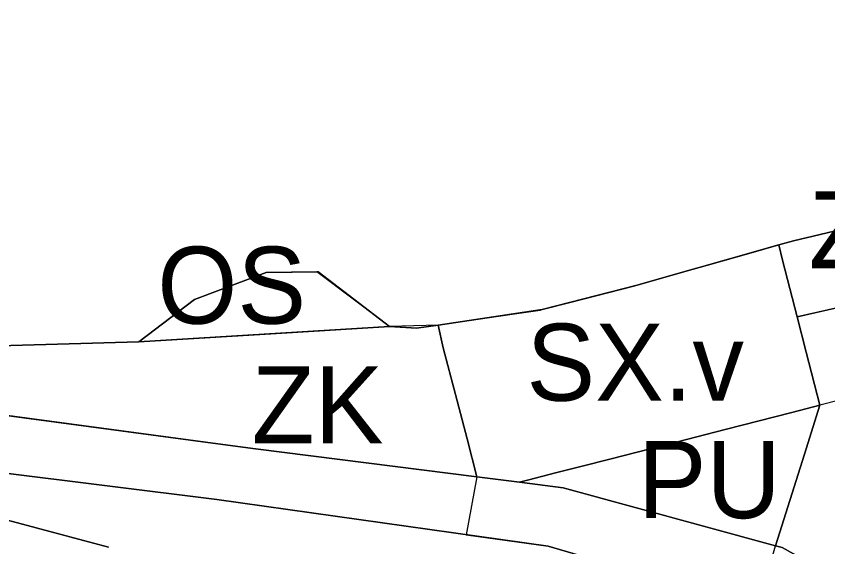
# Model space of a CAD drawing. Extents: x -555509 to -553005, y -1186756 to -1182560.
# Drawn here: x -554216.4 to -554068.9, y -1185302.9 to -1185206.5 of the extents above; entities that cross this region are included whole.
import ezdxf

# ---------------------------------------------------------------- set-up
doc = ezdxf.new("R2010")
doc.units = 0
for name, color, linetype in [('Level 15', 7, 'Continuous'), ('Level 26', 7, 'Continuous'), ('Level 36', 7, 'Continuous'), ('Level 52', 7, 'Continuous'), ('Level 59', 7, 'Continuous'), ('Level 6', 7, 'Continuous'), ('OBRYS_PLOCH', 7, 'Continuous'), ('stav_DS', 7, 'Continuous'), ('stav_OS', 7, 'Continuous'), ('stav_PU', 7, 'Continuous'), ('stav_SX', 7, 'Continuous'), ('stav_ZK', 7, 'Continuous'), ('stav_ZZ', 7, 'Continuous')]:
    doc.layers.add(name, color=color, linetype=linetype)

msp = doc.modelspace()

# ---------------------------------------------------------------- linework, layer by layer
at = {"layer": 'Level 15'}
for points in [[(-554070.29, -1185277.21), (-554075.36, -1185278.51), (-554087.47, -1185281.6), (-554096.17, -1185283.83), (-554108.47, -1185286.99), (-554113.5, -1185288.27), (-554118.34, -1185289.51), (-554123.18, -1185290.75), (-554124.88, -1185291.19)], [(-554078.34, -1185302.74), (-554073.1, -1185286.11), (-554070.29, -1185277.21)], [(-554124.88, -1185291.19), (-554116.97, -1185292.2), (-554078.34, -1185302.74)]]:
    msp.add_lwpolyline(points, dxfattribs=at)
at = {"layer": 'Level 26'}
for points in [[(-553976.73, -1185203.21), (-553980.01, -1185209.02), (-553983.66, -1185211.53), (-554006.5, -1185227.26), (-554018.08, -1185235.23), (-554046.19, -1185248.33), (-554062.2, -1185252.34), (-554060.74, -1185258.05), (-554074.42, -1185261.1), (-554072.76, -1185267.53), (-554070.29, -1185277.21)], [(-554070.29, -1185277.21), (-554073.1, -1185286.11), (-554078.34, -1185302.74), (-554077.12, -1185303.07), (-554067.41, -1185308.49), (-554061.58, -1185289.53), (-554056.72, -1185273.74), (-554044.05, -1185254.33), (-554020.12, -1185246.87), (-554002.44, -1185238.44)]]:
    msp.add_lwpolyline(points, dxfattribs=at)
at = {"layer": 'Level 36'}
msp.add_lwpolyline([(-554056.72, -1185273.74), (-554070.29, -1185277.21), (-554074.42, -1185261.1), (-554077.76, -1185248.04), (-554103.47, -1185255.37), (-554120.79, -1185259.82), (-554139.67, -1185262.64), (-554148.51, -1185262.91), (-554161.7, -1185252.94), (-554170.93, -1185253.07), (-554183.94, -1185257.96), (-554194.09, -1185265.67), (-554225.84, -1185266.59), (-554262.63, -1185260.23), (-554272.08, -1185257.92), (-554272.75, -1185257.67)], dxfattribs=at)
at = {"layer": 'Level 52'}
for points in [[(-554132.61, -1185290.21), (-554134.6, -1185300.73), (-554119.67, -1185302.84), (-554081.51, -1185313.86), (-554078.34, -1185302.74), (-554073.1, -1185286.11), (-554070.29, -1185277.21), (-554072.76, -1185267.53), (-554074.42, -1185261.1), (-554077.08, -1185250.83), (-554077.76, -1185248.04), (-554082.77, -1185249.46), (-554090.71, -1185251.72), (-554094.81, -1185252.89), (-554103.47, -1185255.37), (-554104.18, -1185255.57), (-554115.76, -1185258.54), (-554120.79, -1185259.82), (-554121.12, -1185259.91), (-554125.82, -1185260.59), (-554130.76, -1185261.33), (-554135.22, -1185261.99), (-554139.67, -1185262.64), (-554138.77, -1185266.78), (-554136.52, -1185275.25), (-554134.38, -1185283.3), (-554132.61, -1185290.21)], [(-554169.1, -1185264.16), (-554148.51, -1185262.91), (-554161.7, -1185252.94), (-554170.93, -1185253.07), (-554183.94, -1185257.96), (-554194.09, -1185265.67), (-554169.1, -1185264.16)]]:
    msp.add_lwpolyline(points, dxfattribs=at)
at = {"layer": 'Level 6'}
for points in [[(-554132.61, -1185290.21), (-554134.6, -1185300.73), (-554119.67, -1185302.84), (-554081.51, -1185313.86), (-554078.34, -1185302.74), (-554073.1, -1185286.11), (-554070.29, -1185277.21), (-554072.76, -1185267.53), (-554074.42, -1185261.1), (-554077.08, -1185250.83), (-554077.76, -1185248.04), (-554082.77, -1185249.46), (-554090.71, -1185251.72), (-554094.81, -1185252.89), (-554103.47, -1185255.37), (-554104.18, -1185255.57), (-554115.76, -1185258.54), (-554120.79, -1185259.82), (-554121.12, -1185259.91), (-554125.82, -1185260.59), (-554130.76, -1185261.33), (-554135.22, -1185261.99), (-554139.67, -1185262.64), (-554138.77, -1185266.78), (-554136.52, -1185275.25), (-554134.38, -1185283.3), (-554132.61, -1185290.21)], [(-554169.1, -1185264.16), (-554148.51, -1185262.91), (-554161.7, -1185252.94), (-554170.93, -1185253.07), (-554183.94, -1185257.96), (-554194.09, -1185265.67), (-554169.1, -1185264.16)]]:
    msp.add_lwpolyline(points, dxfattribs=at)
at = {"layer": 'OBRYS_PLOCH'}
for p, q in [((-554075.07, -1185247.28), (-554064.16, -1185244.68)), ((-554064.16, -1185244.68), (-554075.07, -1185247.28)), ((-554077.76, -1185248.04), (-554075.07, -1185247.28)), ((-554075.07, -1185247.28), (-554077.76, -1185248.04)), ((-554082.77, -1185249.46), (-554077.76, -1185248.04)), ((-554090.71, -1185251.72), (-554082.77, -1185249.46)), ((-554161.7, -1185252.94), (-554161.72, -1185252.94)), ((-554161.45, -1185252.94), (-554161.7, -1185252.94)), ((-554161.45, -1185252.94), (-554148.51, -1185262.91)), ((-554148.51, -1185262.91), (-554161.45, -1185252.94)), ((-554115.76, -1185258.54), (-554104.18, -1185255.57)), ((-554104.18, -1185255.57), (-554103.47, -1185255.37)), ((-554120.79, -1185259.82), (-554115.76, -1185258.54)), ((-554074.42, -1185261.1), (-554060.74, -1185258.05)), ((-554130.76, -1185261.33), (-554125.82, -1185260.59)), ((-554125.82, -1185260.59), (-554121.12, -1185259.91)), ((-554121.12, -1185259.91), (-554120.79, -1185259.82)), ((-554139.67, -1185262.64), (-554135.22, -1185261.99)), ((-554135.22, -1185261.99), (-554130.76, -1185261.33)), ((-554148.51, -1185262.91), (-554194.09, -1185265.67)), ((-554194.09, -1185265.67), (-554148.51, -1185262.91)), ((-554148.51, -1185262.91), (-554143.63, -1185263.21)), ((-554143.63, -1185263.21), (-554148.51, -1185262.91)), ((-554143.63, -1185263.21), (-554139.67, -1185262.64)), ((-554139.67, -1185262.64), (-554143.63, -1185263.21)), ((-554134.38, -1185283.3), (-554136.52, -1185275.25)), ((-554178.81, -1185284.35), (-554233.6, -1185276.98)), ((-554134.38, -1185283.3), (-554132.61, -1185290.21)), ((-554132.61, -1185290.21), (-554134.38, -1185283.3)), ((-554235.43, -1185287.38), (-554179.88, -1185294.33)), ((-554179.88, -1185294.33), (-554235.43, -1185287.38)), ((-554199.59, -1185303), (-554237.4, -1185292.88)), ((-554237.4, -1185292.88), (-554199.59, -1185303)), ((-554179.88, -1185294.33), (-554119.67, -1185302.84)), ((-554119.67, -1185302.84), (-554179.88, -1185294.33)), ((-554119.67, -1185302.84), (-554086.79, -1185312.33)), ((-554086.79, -1185312.33), (-554119.67, -1185302.84))]:
    msp.add_line(p, q, dxfattribs=at)
for points in [[(-553976.73, -1185203.21), (-553980.01, -1185209.02), (-553983.66, -1185211.53), (-554006.5, -1185227.26), (-554018.08, -1185235.23), (-554046.19, -1185248.33), (-554062.2, -1185252.34), (-554060.74, -1185258.05), (-554074.42, -1185261.1), (-554072.76, -1185267.53), (-554070.29, -1185277.21)], [(-554070.29, -1185277.21), (-554073.1, -1185286.11), (-554078.34, -1185302.74), (-554077.12, -1185303.07), (-554067.41, -1185308.49), (-554061.58, -1185289.53), (-554056.72, -1185273.74), (-554044.05, -1185254.33), (-554020.12, -1185246.87), (-554002.44, -1185238.44)], [(-554070.29, -1185277.21), (-554072.76, -1185267.53), (-554074.42, -1185261.1), (-554077.08, -1185250.83), (-554077.76, -1185248.04), (-554082.77, -1185249.46), (-554090.71, -1185251.72), (-554094.81, -1185252.89), (-554103.47, -1185255.37)], [(-554077.76, -1185248.04), (-554077.08, -1185250.83), (-554074.42, -1185261.1)], [(-554103.47, -1185255.37), (-554094.81, -1185252.89), (-554090.71, -1185251.72)], [(-554194.09, -1185265.67), (-554183.94, -1185257.96), (-554170.93, -1185253.07), (-554161.45, -1185252.94)], [(-554161.72, -1185252.94), (-554170.93, -1185253.07), (-554183.94, -1185257.96), (-554194.09, -1185265.67)], [(-554103.47, -1185255.37), (-554104.18, -1185255.57), (-554115.76, -1185258.54), (-554120.79, -1185259.82)], [(-554272.75, -1185257.67), (-554272.24, -1185257.88), (-554262.63, -1185260.23), (-554225.84, -1185266.59), (-554194.09, -1185265.67)], [(-554194.09, -1185265.67), (-554225.84, -1185266.59), (-554262.63, -1185260.23), (-554272.24, -1185257.88), (-554272.75, -1185257.67)], [(-554120.79, -1185259.82), (-554121.12, -1185259.91), (-554125.82, -1185260.59), (-554130.76, -1185261.33), (-554135.22, -1185261.99), (-554139.67, -1185262.64), (-554138.77, -1185266.78), (-554136.52, -1185275.25), (-554134.38, -1185283.3)], [(-554136.52, -1185275.25), (-554138.77, -1185266.78), (-554139.67, -1185262.64)], [(-554265.9, -1185267.95), (-554233.6, -1185276.98), (-554178.81, -1185284.35), (-554172.86, -1185285.1), (-554132.61, -1185290.21)], [(-554070.29, -1185277.21), (-554075.36, -1185278.51), (-554087.47, -1185281.6), (-554096.17, -1185283.83), (-554108.47, -1185286.99), (-554113.5, -1185288.27), (-554118.34, -1185289.51), (-554123.18, -1185290.75), (-554124.88, -1185291.19)], [(-554096.17, -1185283.83), (-554087.47, -1185281.6), (-554075.36, -1185278.51), (-554070.29, -1185277.21)], [(-554078.34, -1185302.74), (-554073.1, -1185286.11), (-554070.29, -1185277.21)], [(-554113.5, -1185288.27), (-554108.47, -1185286.99), (-554096.17, -1185283.83)], [(-554132.61, -1185290.21), (-554172.86, -1185285.1), (-554178.81, -1185284.35)], [(-554124.88, -1185291.19), (-554123.18, -1185290.75), (-554118.34, -1185289.51), (-554113.5, -1185288.27)], [(-554132.61, -1185290.21), (-554127.8, -1185290.82), (-554124.88, -1185291.19)], [(-554124.88, -1185291.19), (-554127.8, -1185290.82), (-554132.61, -1185290.21)], [(-554124.88, -1185291.19), (-554116.97, -1185292.2), (-554078.34, -1185302.74)], [(-554078.34, -1185302.74), (-554116.97, -1185292.2), (-554124.88, -1185291.19)], [(-554067.41, -1185308.49), (-554077.12, -1185303.07), (-554078.34, -1185302.74)]]:
    msp.add_lwpolyline(points, dxfattribs=at)
at = {"layer": 'stav_DS'}
for p, q in [((-554235.43, -1185287.38), (-554179.88, -1185294.33)), ((-554116.97, -1185292.2), (-554124.88, -1185291.19)), ((-554078.34, -1185302.74), (-554116.97, -1185292.2))]:
    msp.add_line(p, q, dxfattribs=at)
for points in [[(-554132.61, -1185290.21), (-554172.86, -1185285.1), (-554178.81, -1185284.35), (-554233.6, -1185276.98), (-554265.9, -1185267.95)], [(-554124.88, -1185291.19), (-554127.8, -1185290.82), (-554132.61, -1185290.21)], [(-554179.88, -1185294.33), (-554119.67, -1185302.84), (-554086.79, -1185312.33), (-554081.51, -1185313.86), (-554066.15, -1185321.95), (-554045.89, -1185338.45)], [(-554067.41, -1185308.49), (-554077.12, -1185303.07), (-554078.34, -1185302.74)]]:
    msp.add_lwpolyline(points, dxfattribs=at)
at = {"layer": 'stav_OS'}
for p, q in [((-554161.7, -1185252.94), (-554161.72, -1185252.94)), ((-554161.45, -1185252.94), (-554161.7, -1185252.94)), ((-554148.51, -1185262.91), (-554161.45, -1185252.94)), ((-554194.09, -1185265.67), (-554148.51, -1185262.91))]:
    msp.add_line(p, q, dxfattribs=at)
msp.add_lwpolyline([(-554161.72, -1185252.94), (-554170.93, -1185253.07), (-554183.94, -1185257.96), (-554194.09, -1185265.67)], dxfattribs=at)
at = {"layer": 'stav_PU'}
for points in [[(-554070.29, -1185277.21), (-554075.36, -1185278.51), (-554087.47, -1185281.6), (-554096.17, -1185283.83), (-554108.47, -1185286.99), (-554113.5, -1185288.27), (-554118.34, -1185289.51), (-554123.18, -1185290.75), (-554124.88, -1185291.19)], [(-554078.34, -1185302.74), (-554073.1, -1185286.11), (-554070.29, -1185277.21)], [(-554124.88, -1185291.19), (-554116.97, -1185292.2), (-554078.34, -1185302.74)]]:
    msp.add_lwpolyline(points, dxfattribs=at)
at = {"layer": 'stav_SX'}
msp.add_line((-554134.38, -1185283.3), (-554132.61, -1185290.21), dxfattribs=at)
for points in [[(-554070.29, -1185277.21), (-554072.76, -1185267.53), (-554074.42, -1185261.1), (-554077.08, -1185250.83), (-554077.76, -1185248.04), (-554082.77, -1185249.46), (-554090.71, -1185251.72), (-554094.81, -1185252.89), (-554103.47, -1185255.37)], [(-554103.47, -1185255.37), (-554104.18, -1185255.57), (-554115.76, -1185258.54), (-554120.79, -1185259.82)], [(-554120.79, -1185259.82), (-554121.12, -1185259.91), (-554125.82, -1185260.59), (-554130.76, -1185261.33), (-554135.22, -1185261.99), (-554139.67, -1185262.64), (-554138.77, -1185266.78), (-554136.52, -1185275.25), (-554134.38, -1185283.3)], [(-554096.17, -1185283.83), (-554087.47, -1185281.6), (-554075.36, -1185278.51), (-554070.29, -1185277.21)], [(-554113.5, -1185288.27), (-554108.47, -1185286.99), (-554096.17, -1185283.83)], [(-554124.88, -1185291.19), (-554123.18, -1185290.75), (-554118.34, -1185289.51), (-554113.5, -1185288.27)], [(-554132.61, -1185290.21), (-554127.8, -1185290.82), (-554124.88, -1185291.19)]]:
    msp.add_lwpolyline(points, dxfattribs=at)
at = {"layer": 'stav_ZK'}
for p, q in [((-554064.16, -1185244.68), (-554075.07, -1185247.28)), ((-554075.07, -1185247.28), (-554077.76, -1185248.04)), ((-554074.42, -1185261.1), (-554060.74, -1185258.05)), ((-554148.51, -1185262.91), (-554194.09, -1185265.67)), ((-554143.63, -1185263.21), (-554148.51, -1185262.91)), ((-554139.67, -1185262.64), (-554143.63, -1185263.21)), ((-554134.38, -1185283.3), (-554136.52, -1185275.25)), ((-554132.61, -1185290.21), (-554134.38, -1185283.3)), ((-554179.88, -1185294.33), (-554235.43, -1185287.38)), ((-554237.4, -1185292.88), (-554199.59, -1185303)), ((-554119.67, -1185302.84), (-554179.88, -1185294.33)), ((-554086.79, -1185312.33), (-554119.67, -1185302.84))]:
    msp.add_line(p, q, dxfattribs=at)
for points in [[(-554077.76, -1185248.04), (-554077.08, -1185250.83), (-554074.42, -1185261.1)], [(-554194.09, -1185265.67), (-554225.84, -1185266.59), (-554262.63, -1185260.23), (-554272.24, -1185257.88), (-554272.75, -1185257.67)], [(-554136.52, -1185275.25), (-554138.77, -1185266.78), (-554139.67, -1185262.64)], [(-554265.9, -1185267.95), (-554233.6, -1185276.98), (-554178.81, -1185284.35), (-554172.86, -1185285.1), (-554132.61, -1185290.21)]]:
    msp.add_lwpolyline(points, dxfattribs=at)
at = {"layer": 'stav_ZZ'}
for p, q in [((-554075.07, -1185247.28), (-554064.16, -1185244.68)), ((-554077.76, -1185248.04), (-554075.07, -1185247.28)), ((-554082.77, -1185249.46), (-554077.76, -1185248.04)), ((-554090.71, -1185251.72), (-554082.77, -1185249.46)), ((-554161.45, -1185252.94), (-554148.51, -1185262.91)), ((-554115.76, -1185258.54), (-554104.18, -1185255.57)), ((-554104.18, -1185255.57), (-554103.47, -1185255.37)), ((-554120.79, -1185259.82), (-554115.76, -1185258.54)), ((-554130.76, -1185261.33), (-554125.82, -1185260.59)), ((-554125.82, -1185260.59), (-554121.12, -1185259.91)), ((-554121.12, -1185259.91), (-554120.79, -1185259.82)), ((-554139.67, -1185262.64), (-554135.22, -1185261.99)), ((-554135.22, -1185261.99), (-554130.76, -1185261.33)), ((-554148.51, -1185262.91), (-554143.63, -1185263.21)), ((-554143.63, -1185263.21), (-554139.67, -1185262.64)), ((-554199.59, -1185303), (-554237.4, -1185292.88))]:
    msp.add_line(p, q, dxfattribs=at)
for points in [[(-554103.47, -1185255.37), (-554094.81, -1185252.89), (-554090.71, -1185251.72)], [(-554194.09, -1185265.67), (-554183.94, -1185257.96), (-554170.93, -1185253.07), (-554161.45, -1185252.94)], [(-554272.75, -1185257.67), (-554272.24, -1185257.88), (-554262.63, -1185260.23), (-554225.84, -1185266.59), (-554194.09, -1185265.67)]]:
    msp.add_lwpolyline(points, dxfattribs=at)

# ---------------------------------------------------------------- texts
at = {"layer": 'Level 59'}
for s, p in [('ZK', (-554072.31, -1185252.3)), ('OS', (-554190.72, -1185262.37)), ('SX.v', (-554123.62, -1185276.37)), ('ZK', (-554173.54, -1185284.1)), ('PU', (-554103.38, -1185297.72))]:
    msp.add_text(s, height=14, dxfattribs=at).set_placement(p)

doc.saveas('drawing.dxf')
